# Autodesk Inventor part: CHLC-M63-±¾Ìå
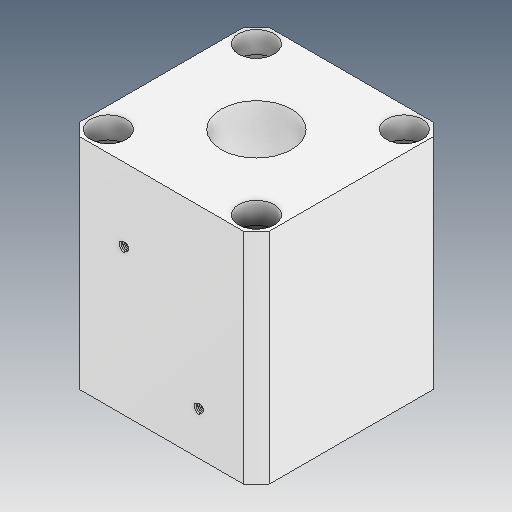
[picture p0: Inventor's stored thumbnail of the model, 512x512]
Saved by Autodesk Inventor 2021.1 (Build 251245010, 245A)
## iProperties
Created: 2021-05
Part Number: CHLC-M63-±¾Ìå
Material: Ogólny
Document SubType Name: Modeling
Designer: user
Density: 1 g/cm^3
Appearance: Domyślna
Author: user
Revision Number: ÈÎºÎ
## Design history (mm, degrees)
feature "ÊäÈë1"
node "Bryła1"
